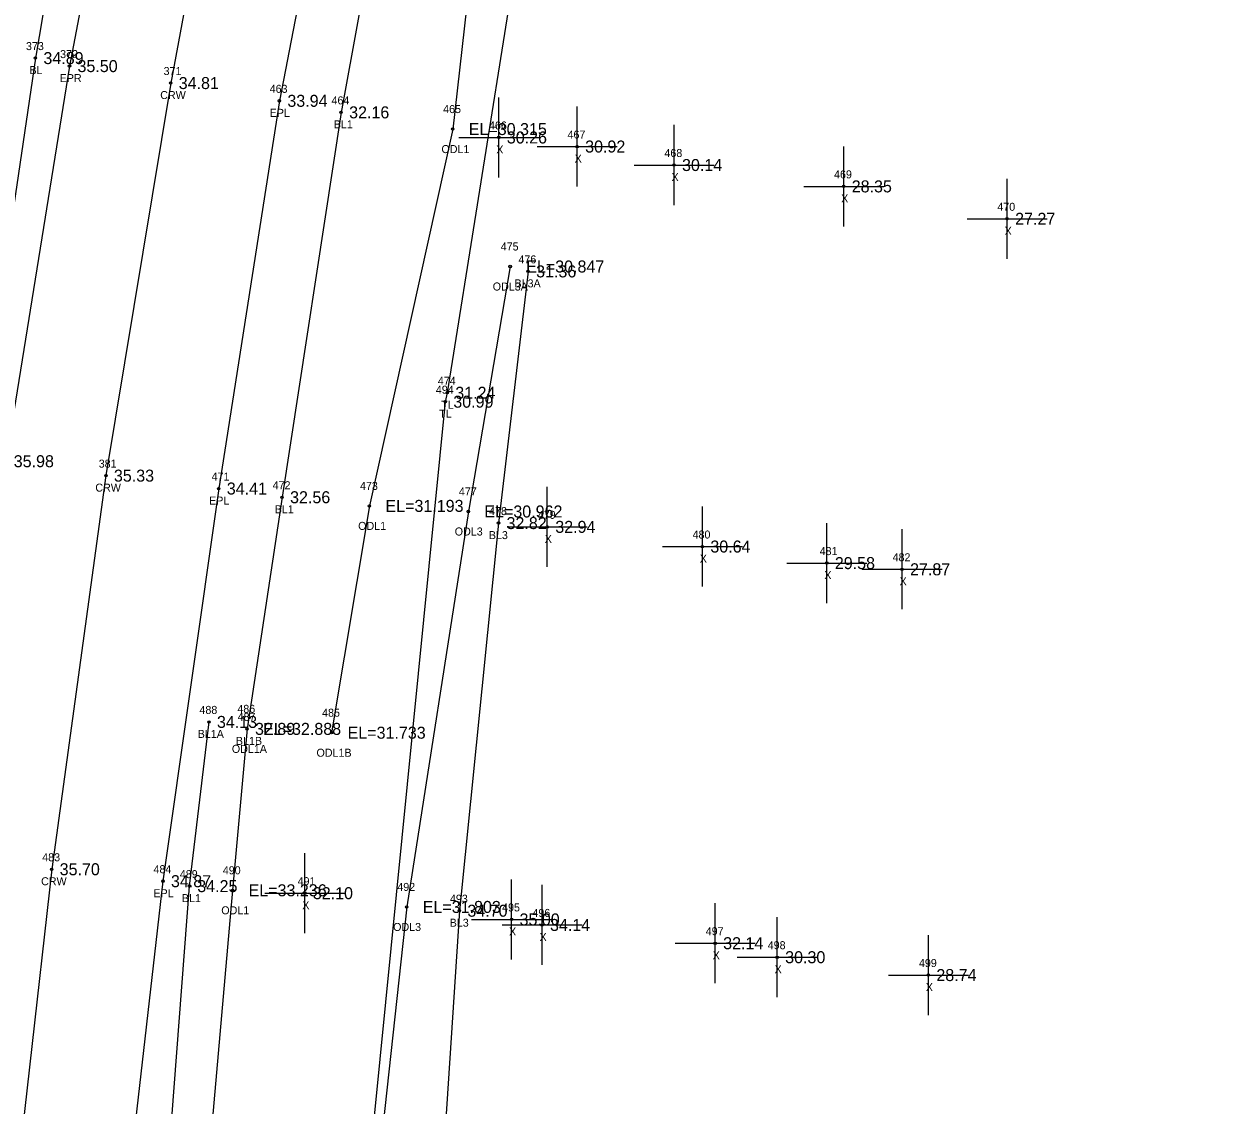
# Model space of a CAD drawing. Extents: x 2042211 to 2045853, y 303080 to 309569.
# Drawn here: x 2042849.9 to 2042999.7, y 307547.4 to 307682.5 of the extents above; entities that cross this region are included whole.
import ezdxf

# ---------------------------------------------------------------- set-up
doc = ezdxf.new("R2010")
doc.units = 0
for name, color, linetype in [('BR_500YR_SCOUR', 7, 'Continuous'), ('RD_DTM_BkLn1', 7, 'Continuous'), ('RD_DTM_BkLn_txCode', 7, 'Continuous'), ('RD_EX_H2O', 7, 'Continuous'), ('RD_EX_H2O_txCode', 7, 'Continuous'), ('RD_EX_Misc', 7, 'Continuous'), ('RD_EX_Misc_txCode', 7, 'Continuous'), ('RD_EX_Road', 7, 'Continuous'), ('RD_EX_Road_txCode', 7, 'Continuous'), ('RD_EX_TX_H2O_ELEV', 7, 'Continuous'), ('RD_EX_TX_Misc_ELEV', 7, 'Continuous'), ('RD_EX_TX_Road_ELEV', 7, 'Continuous'), ('RD_EX_TX_VEG_ELEV', 7, 'Continuous'), ('RD_EX_VEG_txCode', 7, 'Continuous'), ('RD_HC_Survey_ELEV', 7, 'Continuous'), ('RD_HC_Survey_txCode', 7, 'Continuous'), ('RD_SMD_Locator', 7, 'Continuous')]:
    doc.layers.add(name, color=color, linetype=linetype)

msp = doc.modelspace()

# ---------------------------------------------------------------- linework, layer by layer
at = {"layer": 'BR_500YR_SCOUR'}
msp.add_lwpolyline([(2043048.7, 308112.2), (2043032.62, 308087.68), (2043027.55, 308080.82), (2043013.5, 308043.09), (2042994.71, 307997.39), (2042983.47, 307967.75), (2042952.97, 307870.73), (2042935.66, 307809.47), (2042918.92, 307737.74), (2042902.79, 307636.4), (2042902.54, 307635.29), (2042891, 307519.21), (2042885.61, 307482.85), (2042881.1, 307379.92), (2042880.44, 307351.7), (2042880.19, 307284.9)], dxfattribs=at)
for centre in [(2042902.54, 307635.29), (2042902.79, 307636.4)]:
    msp.add_circle(centre, 0.15, dxfattribs=at)
at = {"layer": 'RD_DTM_BkLn1'}
for points in [[(2043161.13, 308408.97), (2043133.81, 308366.92), (2043082.92, 308281.6), (2043059.61, 308238.25), (2043036.96, 308193.55), (2043015.53, 308147.97), (2042995.29, 308102.87), (2042976.3, 308056.87), (2042958.8, 308010.83), (2042942.32, 307963.75), (2042927.06, 307916.53), (2042912.57, 307868.35), (2042899.47, 307820.61), (2042887.68, 307772.41), (2042877.12, 307722.98), (2042868.22, 307675.1), (2042860.12, 307626.05), (2042853.34, 307576.87), (2042847.77, 307527.39), (2042843.87, 307477.74), (2042841.31, 307428.69), (2042840.04, 307379.1), (2042839.81, 307329.37), (2042840.93, 307280.46)], [(2043084.04, 308249.78), (2043074.97, 308230.46), (2043053.22, 308185.62), (2043031.61, 308140.82), (2043017.56, 308093.82), (2042997.77, 308049.45), (2042978.41, 308004.57), (2042961.32, 307957.89), (2042945.16, 307911.22), (2042932.79, 307863.05), (2042919.73, 307815.78), (2042908.87, 307767.34), (2042898.28, 307719.5), (2042889.52, 307671.44), (2042882.14, 307623.35), (2042877.76, 307594.41)], [(2042869.74, 307776.07), (2042859.54, 307726.73), (2042851.31, 307678.22), (2042843.92, 307628.21), (2042836.41, 307578.73), (2042830.84, 307528.85), (2042827.5, 307478.96), (2042824.99, 307429.39), (2042821.8, 307378.88), (2042823.15, 307329.29), (2042823.59, 307279.35)], [(2042912.89, 307651.57), (2042909.19, 307620.12), (2042904.3, 307571.69), (2042901, 307520.89), (2042892.72, 307473.02), (2042890.79, 307426.32), (2042889.47, 307415.14)], [(2042873, 307595.28), (2042870.54, 307574.76), (2042866.75, 307524.99), (2042861.37, 307475.18), (2042860.89, 307427.06), (2042859.12, 307378.9), (2042857.66, 307329.64), (2042861.09, 307281.84)]]:
    msp.add_lwpolyline(points, dxfattribs=at)
at = {"layer": 'RD_EX_H2O'}
for points in [[(2042954.71, 307908), (2042941.87, 307861.24), (2042931.11, 307813.3), (2042918.51, 307765.02), (2042908.96, 307717.68), (2042903.47, 307669.35), (2042893.06, 307622.27), (2042888.33, 307593.93)], [(2042910.65, 307652.18), (2042905.42, 307621.57), (2042897.72, 307572.16), (2042892.26, 307522.14), (2042886.65, 307473.55), (2042887.85, 307426.41), (2042886.57, 307414.7)], [(2042877.76, 307594.41), (2042875.95, 307574.24), (2042871.62, 307524.91), (2042871.88, 307474.1), (2042865.43, 307427.05), (2042866.84, 307378.87), (2042866.82, 307329.93), (2042876.23, 307282.16)]]:
    msp.add_lwpolyline(points, dxfattribs=at)
at = {"layer": 'RD_EX_Misc'}
for p, q in [((2042909.23, 307663.3), (2042909.23, 307673.3)), ((2042919.02, 307662.17), (2042919.02, 307672.17)), ((2042931.13, 307659.86), (2042931.13, 307669.86)), ((2042904.23, 307668.3), (2042914.23, 307668.3)), ((2042914.02, 307667.17), (2042924.02, 307667.17)), ((2042952.34, 307657.19), (2042952.34, 307667.19)), ((2042926.13, 307664.86), (2042936.13, 307664.86)), ((2042947.34, 307662.19), (2042957.34, 307662.19)), ((2042972.76, 307653.14), (2042972.76, 307663.14)), ((2042967.76, 307658.14), (2042977.76, 307658.14)), ((2042915.29, 307614.65), (2042915.29, 307624.65)), ((2042934.67, 307612.19), (2042934.67, 307622.19)), ((2042950.23, 307610.12), (2042950.23, 307620.12)), ((2042910.29, 307619.65), (2042920.29, 307619.65)), ((2042959.63, 307609.35), (2042959.63, 307619.35)), ((2042929.67, 307617.19), (2042939.67, 307617.19)), ((2042945.23, 307615.12), (2042955.23, 307615.12)), ((2042954.63, 307614.35), (2042964.63, 307614.35)), ((2042884.98, 307568.88), (2042884.98, 307578.88)), ((2042910.82, 307565.6), (2042910.82, 307575.6)), ((2042879.98, 307573.88), (2042889.98, 307573.88)), ((2042914.63, 307564.91), (2042914.63, 307574.91)), ((2042936.27, 307562.63), (2042936.27, 307572.63)), ((2042944.02, 307560.88), (2042944.02, 307570.88)), ((2042905.82, 307570.6), (2042915.82, 307570.6)), ((2042909.63, 307569.91), (2042919.63, 307569.91)), ((2042962.92, 307558.65), (2042962.92, 307568.65)), ((2042931.27, 307567.63), (2042941.27, 307567.63)), ((2042939.02, 307565.88), (2042949.02, 307565.88)), ((2042957.92, 307563.65), (2042967.92, 307563.65))]:
    msp.add_line(p, q, dxfattribs=at)
at = {"layer": 'RD_EX_Road'}
for points in [[(2042912.69, 307817.39), (2042901.29, 307769.38), (2042891.09, 307720.95), (2042881.8, 307672.88), (2042874.23, 307624.44), (2042867.25, 307575.38), (2042861.55, 307525.78), (2042857.62, 307475.83), (2042855.03, 307427.78), (2042853.64, 307379.19), (2042853.31, 307329.44), (2042854.43, 307281.38)], [(2042875.38, 307775.02), (2042864.88, 307726.03), (2042855.57, 307677.22), (2042847.6, 307627.85), (2042840.73, 307578.32), (2042835.07, 307528.58), (2042830.98, 307478.6), (2042828.36, 307428.87), (2042826.99, 307378.91), (2042826.88, 307329.29), (2042828.01, 307279.82)]]:
    msp.add_lwpolyline(points, dxfattribs=at)
at = {"layer": 'RD_SMD_Locator'}
for centre in [(2042851.31, 307678.22), (2042855.57, 307677.22), (2042868.22, 307675.1), (2042881.8, 307672.88), (2042889.52, 307671.44), (2042903.47, 307669.35), (2042909.23, 307668.3), (2042919.02, 307667.17), (2042931.13, 307664.86), (2042952.34, 307662.19), (2042972.76, 307658.14), (2042910.65, 307652.18), (2042912.89, 307651.57), (2042860.12, 307626.05), (2042874.23, 307624.44), (2042882.14, 307623.35), (2042893.06, 307622.27), (2042905.42, 307621.57), (2042909.19, 307620.12), (2042915.29, 307619.65), (2042934.67, 307617.19), (2042950.23, 307615.12), (2042959.63, 307614.35), (2042873, 307595.28), (2042877.76, 307594.41), (2042877.76, 307594.41), (2042888.33, 307593.93), (2042853.34, 307576.87), (2042867.25, 307575.38), (2042870.54, 307574.76), (2042875.95, 307574.24), (2042884.98, 307573.88), (2042897.72, 307572.16), (2042904.3, 307571.69), (2042910.82, 307570.6), (2042914.63, 307569.91), (2042936.27, 307567.63), (2042944.02, 307565.88), (2042962.92, 307563.65)]:
    msp.add_circle(centre, 0.15, dxfattribs=at)

# ---------------------------------------------------------------- texts
at = {"layer": 'RD_DTM_BkLn_txCode'}
for s, p in [('373', (2042850.13, 307679.22)), ('BL', (2042850.56, 307676.22)), ('464', (2042888.32, 307672.44)), ('BL1', (2042888.6, 307669.44)), ('476', (2042911.68, 307652.57)), ('BL3A', (2042911.19, 307649.57)), ('472', (2042880.96, 307624.35)), ('BL1', (2042881.22, 307621.35)), ('478', (2042908.01, 307621.12)), ('BL3', (2042907.98, 307618.12)), ('488', (2042871.81, 307596.28)), ('487', (2042876.58, 307595.41)), ('BL1A', (2042871.59, 307593.28)), ('BL1B', (2042876.37, 307592.41)), ('489', (2042869.36, 307575.76)), ('BL1', (2042869.62, 307572.76)), ('493', (2042903.12, 307572.69)), ('BL3', (2042903.09, 307569.69))]:
    msp.add_text(s, height=1, dxfattribs=at).set_placement(p)
at = {"layer": 'RD_EX_H2O_txCode'}
for s, p in [('465', (2042902.27, 307671.35)), ('ODL1', (2042902.06, 307666.35)), ('475', (2042909.47, 307654.18)), ('ODL3A', (2042908.47, 307649.18)), ('473', (2042891.88, 307624.27)), ('477', (2042904.24, 307623.57)), ('ODL1', (2042891.65, 307619.27)), ('ODL3', (2042903.72, 307618.57)), ('486', (2042876.55, 307596.41)), ('485', (2042887.14, 307595.93)), ('ODL1A', (2042875.86, 307591.41)), ('ODL1B', (2042886.44, 307590.93)), ('490', (2042874.73, 307576.24)), ('492', (2042896.54, 307574.16)), ('ODL1', (2042874.54, 307571.24)), ('ODL3', (2042896.02, 307569.16))]:
    msp.add_text(s, height=1, dxfattribs=at).set_placement(p)
at = {"layer": 'RD_EX_Misc_txCode'}
for s, p in [('466', (2042908, 307669.3)), ('467', (2042917.82, 307668.17)), ('X', (2042908.91, 307666.3)), ('468', (2042929.93, 307665.86)), ('X', (2042918.71, 307665.17)), ('X', (2042930.82, 307662.86)), ('469', (2042951.13, 307663.19)), ('X', (2042952.02, 307660.19)), ('470', (2042971.54, 307659.14)), ('X', (2042972.45, 307656.14)), ('479', (2042914.1, 307620.65)), ('X', (2042914.97, 307617.65)), ('480', (2042933.45, 307618.19)), ('481', (2042949.33, 307616.12)), ('X', (2042934.35, 307615.19)), ('482', (2042958.45, 307615.35)), ('X', (2042949.92, 307613.12)), ('X', (2042959.32, 307612.35)), ('491', (2042884.08, 307574.88)), ('X', (2042884.67, 307571.88)), ('495', (2042909.64, 307571.6)), ('496', (2042913.43, 307570.91)), ('X', (2042910.51, 307568.6)), ('497', (2042935.09, 307568.63)), ('X', (2042914.32, 307567.91)), ('498', (2042942.84, 307566.88)), ('X', (2042935.96, 307565.63)), ('X', (2042943.7, 307563.88)), ('499', (2042961.74, 307564.65)), ('X', (2042962.6, 307561.65))]:
    msp.add_text(s, height=1, dxfattribs=at).set_placement(p)
at = {"layer": 'RD_EX_Road_txCode'}
for s, p in [('372', (2042854.39, 307678.22)), ('EPR', (2042854.34, 307675.22)), ('463', (2042880.59, 307673.88)), ('EPL', (2042880.59, 307670.88)), ('471', (2042873.33, 307625.44)), ('EPL', (2042873.02, 307622.44)), ('484', (2042866.07, 307576.38)), ('EPL', (2042866.05, 307573.38))]:
    msp.add_text(s, height=1, dxfattribs=at).set_placement(p)
at = {"layer": 'RD_EX_TX_H2O_ELEV'}
for s, p in [('EL=30.315', (2042905.47, 307668.6)), ('EL=30.847', (2042912.65, 307651.43)), ('EL=31.193', (2042895.06, 307621.52)), ('EL=30.962', (2042907.42, 307620.82)), ('EL=32.888', (2042879.76, 307593.66)), ('EL=31.733', (2042890.33, 307593.18)), ('EL=33.236', (2042877.95, 307573.49)), ('EL=31.803', (2042899.72, 307571.41))]:
    msp.add_text(s, height=1.5, dxfattribs=at).set_placement(p)
at = {"layer": 'RD_EX_TX_Misc_ELEV'}
for s, p in [('34.89', (2042852.31, 307677.47)), ('32.16', (2042890.52, 307670.69)), ('30.26', (2042910.23, 307667.55)), ('30.92', (2042920.02, 307666.42)), ('30.14', (2042932.13, 307664.11)), ('28.35', (2042953.34, 307661.44)), ('27.27', (2042973.76, 307657.39)), ('31.36', (2042913.89, 307650.82)), ('32.56', (2042883.14, 307622.6)), ('32.82', (2042910.19, 307619.37)), ('32.94', (2042916.29, 307618.9)), ('30.64', (2042935.67, 307616.44)), ('29.58', (2042951.23, 307614.37)), ('27.87', (2042960.63, 307613.6)), ('34.13', (2042874, 307594.53)), ('32.89', (2042878.76, 307593.66)), ('34.25', (2042871.54, 307574.01)), ('32.10', (2042885.98, 307573.13)), ('34.70', (2042905.3, 307570.94)), ('35.00', (2042911.82, 307569.85)), ('34.14', (2042915.63, 307569.16)), ('32.14', (2042937.27, 307566.88)), ('30.30', (2042945.02, 307565.13)), ('28.74', (2042963.92, 307562.9))]:
    msp.add_text(s, height=1.5, dxfattribs=at).set_placement(p)
at = {"layer": 'RD_EX_TX_Road_ELEV'}
for s, p in [('35.50', (2042856.57, 307676.47)), ('33.94', (2042882.8, 307672.13)), ('35.98', (2042848.6, 307627.1)), ('34.41', (2042875.23, 307623.69)), ('34.87', (2042868.25, 307574.63))]:
    msp.add_text(s, height=1.5, dxfattribs=at).set_placement(p)
at = {"layer": 'RD_EX_TX_VEG_ELEV'}
for s, p in [('31.24', (2042903.79, 307635.65)), ('30.99', (2042903.54, 307634.54))]:
    msp.add_text(s, height=1.5, dxfattribs=at).set_placement(p)
at = {"layer": 'RD_EX_VEG_txCode'}
for s, p in [('474', (2042901.61, 307637.4)), ('494', (2042901.36, 307636.29)), ('TL', (2042902.02, 307634.4)), ('TL', (2042901.77, 307633.29))]:
    msp.add_text(s, height=1, dxfattribs=at).set_placement(p)
at = {"layer": 'RD_HC_Survey_ELEV'}
for s, p in [('34.81', (2042869.22, 307674.35)), ('35.33', (2042861.12, 307625.3)), ('35.70', (2042854.34, 307576.12))]:
    msp.add_text(s, height=1.5, dxfattribs=at).set_placement(p)
at = {"layer": 'RD_HC_Survey_txCode'}
for s, p in [('371', (2042867.33, 307676.1)), ('CRW', (2042866.91, 307673.1)), ('381', (2042859.22, 307627.05)), ('CRW', (2042858.8, 307624.05)), ('483', (2042852.16, 307577.87)), ('CRW', (2042852.02, 307574.87))]:
    msp.add_text(s, height=1, dxfattribs=at).set_placement(p)

doc.saveas('drawing.dxf')
